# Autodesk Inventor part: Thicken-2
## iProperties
Shininess: 64.0
Length Units: 11269
Angle Units: 11279
Time Units: 11290
Mass Units: 11283
Length Display Precision: 3
Angle Display Precision: 2
Compacted: True
Part Number: Thicken-2
Document SubType Name: Modeling
Created: 2003-10
Designer: Owner
Manufacturer: Standard
Standards Organization: Custom
Density: 0.0
Volumn: 0.0
Area: 0.0
PropertySet Name: Model Information
Control State: 0
Master: False
Checked Out: False
Author: Owner
